(* Logix 5000 project; controller NXFE2_EDS_AOI_sample_RSLogix_V31 vendor 1 type 14 code 92 rev 31.11; software revision 31.00; part 2 of 4 *)

ADD_ON_INSTRUCTION AMCI_NXFE2_Home_CW   (* revision 1.0, vendor AMCI, ExecuteEnableInFalse *)
VAR_INPUT
   Axis_Status_Bits : INT; {required}
   Programmed_Speed : DINT; {required}
   Acceleration : INT; {required}
   Deceleration : INT; {required}
END_VAR
VAR_IN_OUT
   NXFE2_output_data : _000A:NXFE2_0986AEB4:O:0; {required}
END_VAR
VAR_OUTPUT
   EN : BOOL; {access Read Only, visible}
   ER : BOOL; {access Read Only, visible}
END_VAR
VAR
   command_data_block : INT[10];
        [1]   // Command Bits LSW
        [3]   // Lower Target Position
        [5]   // Lower Programmed Speed
        [0]   // Command Bits MSW
        [2]   // Upper Target Position
        [4]   // Upper Programmed Speed
END_VAR

ROUTINE EnableInFalse   (* ladder *)
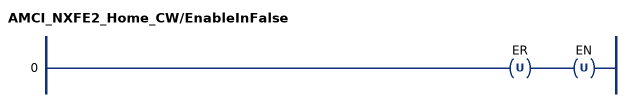
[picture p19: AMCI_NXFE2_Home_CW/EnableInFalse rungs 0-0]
   0: OTU(ER)OTU(EN);
END_ROUTINE

ROUTINE Logic   (* ladder *)
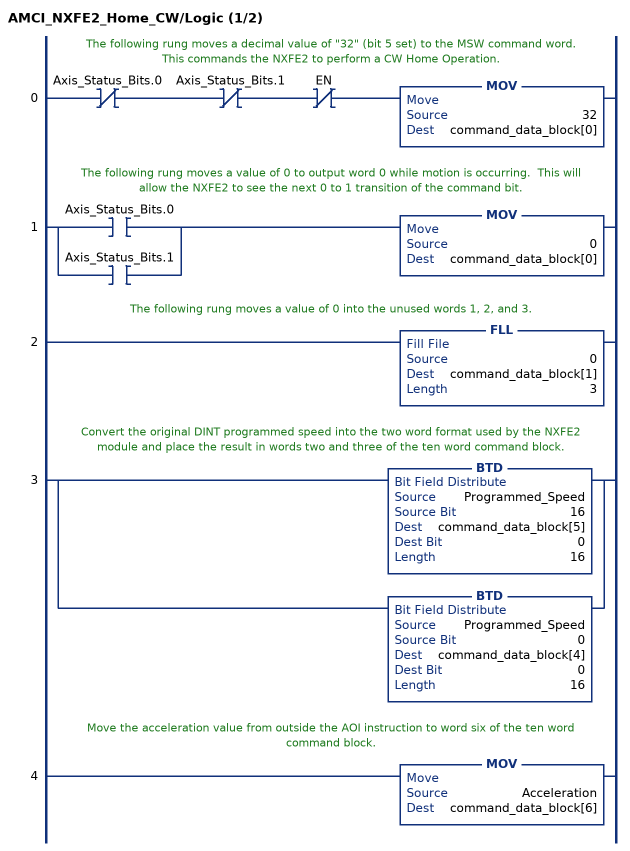
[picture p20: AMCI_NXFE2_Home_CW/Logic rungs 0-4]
   // The following rung moves a decimal value of "32" (bit 5 set) to the MSW command word.  This commands the NXFE2 to perform a CW Home Operation.
   0: XIO(Axis_Status_Bits.0)XIO(Axis_Status_Bits.1)XIO(EN)MOV(32,command_data_block[0]);
   // The following rung moves a value of 0 to output word 0 while motion is occurring.  This will allow the NXFE2 to see the next 0 to 1 transition of the command bit.
   1: [XIC(Axis_Status_Bits.0) ,XIC(Axis_Status_Bits.1) ]MOV(0,command_data_block[0]);
   // The following rung moves a value of 0 into the unused words 1, 2, and 3.
   2: FLL(0,command_data_block[1],3);
   // Convert the original DINT programmed speed into the two word format used by the NXFE2 module and place the result in words two and three of the ten word command block.
   3: [BTD(Programmed_Speed,16,command_data_block[5],0,16) ,BTD(Programmed_Speed,0,command_data_block[4],0,16) ];
   // Move the acceleration value from outside the AOI instruction to word six of the ten word command block.
   4: MOV(Acceleration,command_data_block[6]);
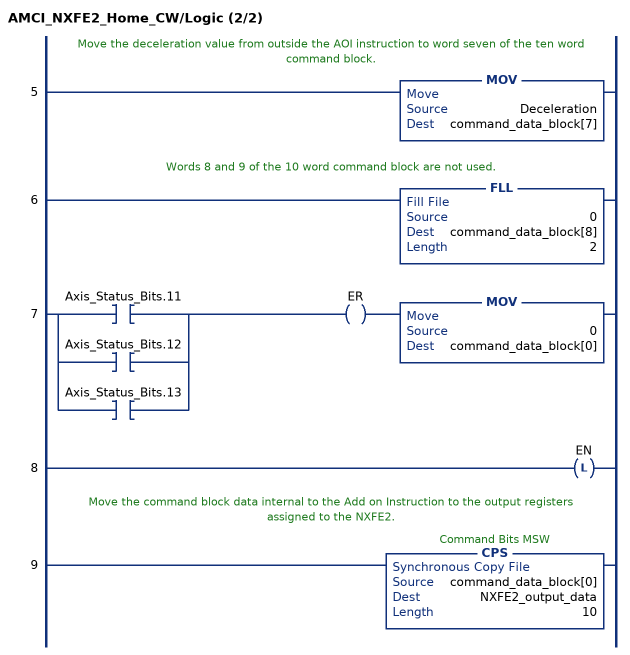
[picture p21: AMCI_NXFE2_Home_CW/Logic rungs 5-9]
   // Move the deceleration value from outside the AOI instruction to word seven of the ten word command block.
   5: MOV(Deceleration,command_data_block[7]);
   // Words 8 and 9 of the 10 word command block are not used.
   6: FLL(0,command_data_block[8],2);
   7: [XIC(Axis_Status_Bits.11) ,XIC(Axis_Status_Bits.12) ,XIC(Axis_Status_Bits.13) ]OTE(ER)MOV(0,command_data_block[0]);
   8: OTL(EN);
   // Move the command block data internal to the Add on Instruction to the output registers assigned to the NXFE2.
   9: CPS(command_data_block[0],NXFE2_output_data,10);
END_ROUTINE
END_ADD_ON_INSTRUCTION

ADD_ON_INSTRUCTION AMCI_NXFE2_Immediate_Stop   (* revision 1.1, vendor AMCI *)
// Revision note:
// Version 1.1 added the slot_axis number and the input parameters can now be tags or discrete values.
VAR_IN_OUT
   NXFE2_output_data : _000A:NXFE2_0986AEB4:O:0; {required}
END_VAR
VAR
   command_data_block : INT[10];
        [1]   // Command Bits LSW
        [3]   // Lower Target Position
        [5]   // Lower Programmed Speed
        [0]   // Command Bits MSW
        [2]   // Upper Target Position
        [4]   // Upper Programmed Speed
END_VAR

ROUTINE Logic   (* ladder *)
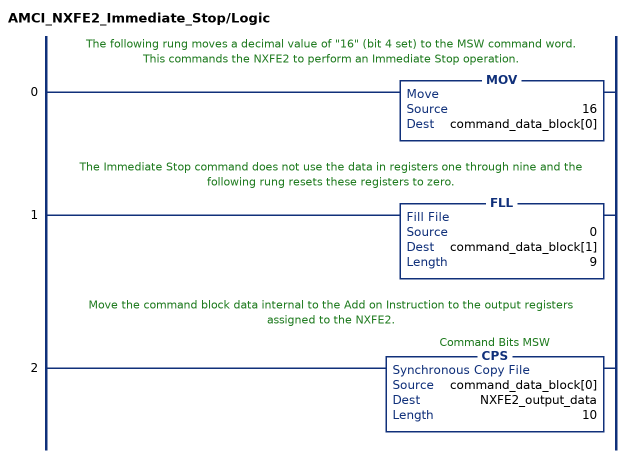
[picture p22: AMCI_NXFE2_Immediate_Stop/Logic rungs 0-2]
   // The following rung moves a decimal value of "16" (bit 4 set) to the MSW command word.  This commands the NXFE2 to perform an Immediate Stop operation.
   0: MOV(16,command_data_block[0]);
   // The Immediate Stop command does not use the data in registers one through nine and the following rung resets these registers to zero.
   1: FLL(0,command_data_block[1],9);
   // Move the command block data internal to the Add on Instruction to the output registers assigned to the NXFE2.
   2: CPS(command_data_block[0],NXFE2_output_data,10);
END_ROUTINE
END_ADD_ON_INSTRUCTION

ADD_ON_INSTRUCTION AMCI_NXFE2_Jog_CCW   (* revision 1.0, vendor AMCI, ExecuteEnableInFalse *)
VAR_INPUT
   Axis_Status_Bits : DINT; {required}
        .1   // Set when moving CCW
   _0_normal_1_S_curve_acceleration : BOOL;
   _0_Triangular_1_Trapezoidal_S_Curve : BOOL;
   Programmed_Speed : DINT; {required}
   Acceleration : INT; {required}
   Deceleration : INT; {required}
END_VAR
VAR_IN_OUT
   NXFE2_output_data : _000A:NXFE2_0986AEB4:O:0; {required}
END_VAR
VAR_OUTPUT
   EN : BOOL; {access Read Only, visible}
   Jog_CCW_Occurring : BOOL; {access Read Only, visible}
   ER : BOOL; {access Read Only, visible}
END_VAR
VAR
   command_data_block : INT[10];
        [1]   // Command Bits LSW
        [3]   // Lower Target Position
        [5]   // Lower Programmed Speed
        [0]   // Command Bits MSW
        [4]   // Upper Programmed Speed
END_VAR

ROUTINE EnableInFalse   (* ladder *)
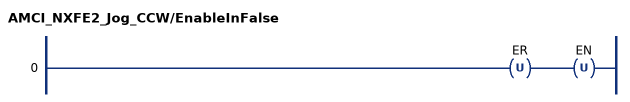
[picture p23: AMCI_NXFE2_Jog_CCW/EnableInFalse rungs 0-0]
   0: OTU(ER)OTU(EN);
END_ROUTINE

ROUTINE Logic   (* ladder *)
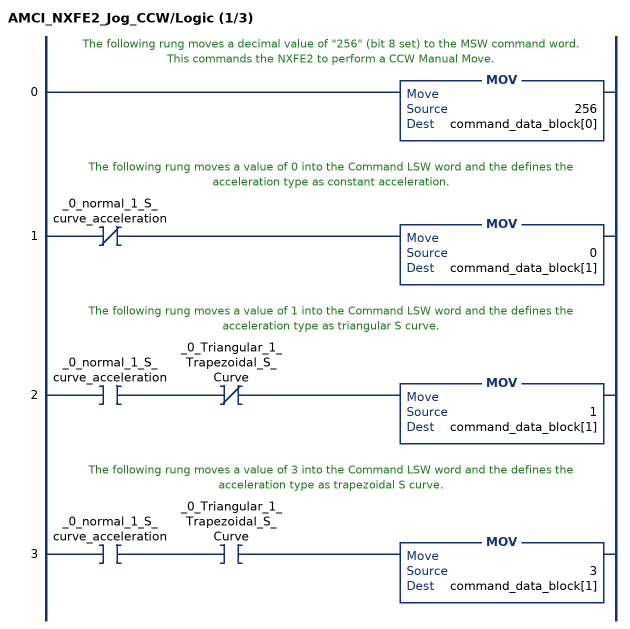
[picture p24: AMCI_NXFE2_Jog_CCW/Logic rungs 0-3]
   // The following rung moves a decimal value of "256" (bit 8 set) to the MSW command word.  This commands the NXFE2 to perform a CCW Manual Move.
   0: MOV(256,command_data_block[0]);
   // The following rung moves a value of 0 into the Command LSW word and the defines the acceleration type as constant acceleration.
   1: XIO(_0_normal_1_S_curve_acceleration)MOV(0,command_data_block[1]);
   // The following rung moves a value of 1 into the Command LSW word and the defines the acceleration type as triangular S curve.
   2: XIC(_0_normal_1_S_curve_acceleration)XIO(_0_Triangular_1_Trapezoidal_S_Curve)MOV(1,command_data_block[1]);
   // The following rung moves a value of 3 into the Command LSW word and the defines the acceleration type as trapezoidal S curve.
   3: XIC(_0_normal_1_S_curve_acceleration)XIC(_0_Triangular_1_Trapezoidal_S_Curve)MOV(3,command_data_block[1]);
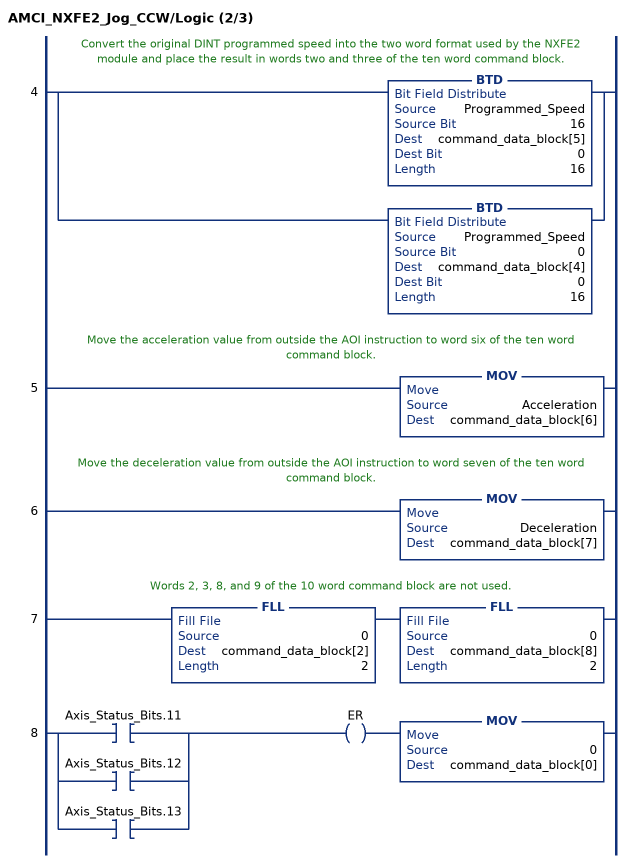
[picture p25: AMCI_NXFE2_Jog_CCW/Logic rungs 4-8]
   // Convert the original DINT programmed speed into the two word format used by the NXFE2 module and place the result in words two and three of the ten word command block.
   4: [BTD(Programmed_Speed,16,command_data_block[5],0,16) ,BTD(Programmed_Speed,0,command_data_block[4],0,16) ];
   // Move the acceleration value from outside the AOI instruction to word six of the ten word command block.
   5: MOV(Acceleration,command_data_block[6]);
   // Move the deceleration value from outside the AOI instruction to word seven of the ten word command block.
   6: MOV(Deceleration,command_data_block[7]);
   // Words 2, 3, 8, and 9 of the 10 word command block are not used.
   7: FLL(0,command_data_block[2],2)FLL(0,command_data_block[8],2);
   8: [XIC(Axis_Status_Bits.11) ,XIC(Axis_Status_Bits.12) ,XIC(Axis_Status_Bits.13) ]OTE(ER)MOV(0,command_data_block[0]);
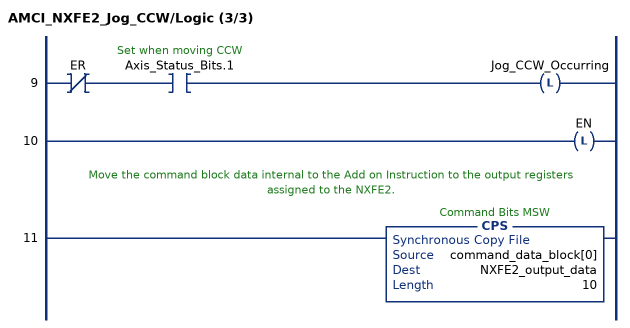
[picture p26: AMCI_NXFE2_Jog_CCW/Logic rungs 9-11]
   9: XIO(ER)XIC(Axis_Status_Bits.1)OTL(Jog_CCW_Occurring);
   10: OTL(EN);
   // Move the command block data internal to the Add on Instruction to the output registers assigned to the NXFE2.
   11: CPS(command_data_block[0],NXFE2_output_data,10);
END_ROUTINE
END_ADD_ON_INSTRUCTION

ADD_ON_INSTRUCTION AMCI_NXFE2_Jog_CW   (* revision 1.0, vendor AMCI, ExecuteEnableInFalse *)
VAR_INPUT
   Axis_Status_Bits : INT; {required}
   _0_normal_1_S_Curve_Acceleration : BOOL;
   _0_Triangular_1_Trapezoidal_S_Curve : BOOL;
   Programmed_Speed : DINT; {required}
   Acceleration : INT; {required}
   Deceleration : INT; {required}
END_VAR
VAR_IN_OUT
   NXFE2_output_data : _000A:NXFE2_0986AEB4:O:0; {required}
END_VAR
VAR_OUTPUT
   EN : BOOL; {access Read Only, visible}
   Jog_CW_Occurring : BOOL; {access Read Only, visible}
   ER : BOOL; {access Read Only, visible}
END_VAR
VAR
   command_data_block : INT[10];
        [1]   // Command Bits LSW
        [3]   // Lower Target Position
        [5]   // Lower Programmed Speed
        [0]   // Command Bits MSW
        [4]   // Upper Programmed Speed
END_VAR

ROUTINE EnableInFalse   (* ladder *)
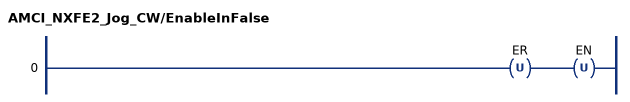
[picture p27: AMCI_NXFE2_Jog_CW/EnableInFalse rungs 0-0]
   0: OTU(ER)OTU(EN);
END_ROUTINE

ROUTINE Logic   (* ladder *)
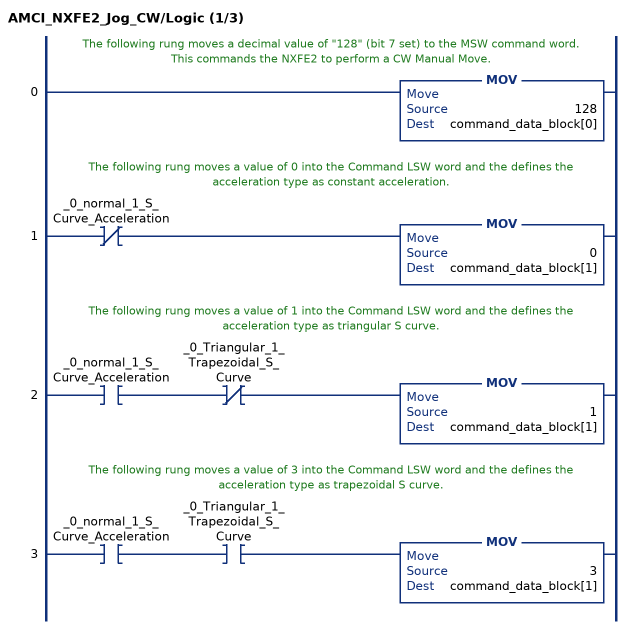
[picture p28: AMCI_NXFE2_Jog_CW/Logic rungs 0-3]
   // The following rung moves a decimal value of "128" (bit 7 set) to the MSW command word.  This commands the NXFE2 to perform a CW Manual Move.
   0: MOV(128,command_data_block[0]);
   // The following rung moves a value of 0 into the Command LSW word and the defines the acceleration type as constant acceleration.
   1: XIO(_0_normal_1_S_Curve_Acceleration)MOV(0,command_data_block[1]);
   // The following rung moves a value of 1 into the Command LSW word and the defines the acceleration type as triangular S curve.
   2: XIC(_0_normal_1_S_Curve_Acceleration)XIO(_0_Triangular_1_Trapezoidal_S_Curve)MOV(1,command_data_block[1]);
   // The following rung moves a value of 3 into the Command LSW word and the defines the acceleration type as trapezoidal S curve.
   3: XIC(_0_normal_1_S_Curve_Acceleration)XIC(_0_Triangular_1_Trapezoidal_S_Curve)MOV(3,command_data_block[1]);
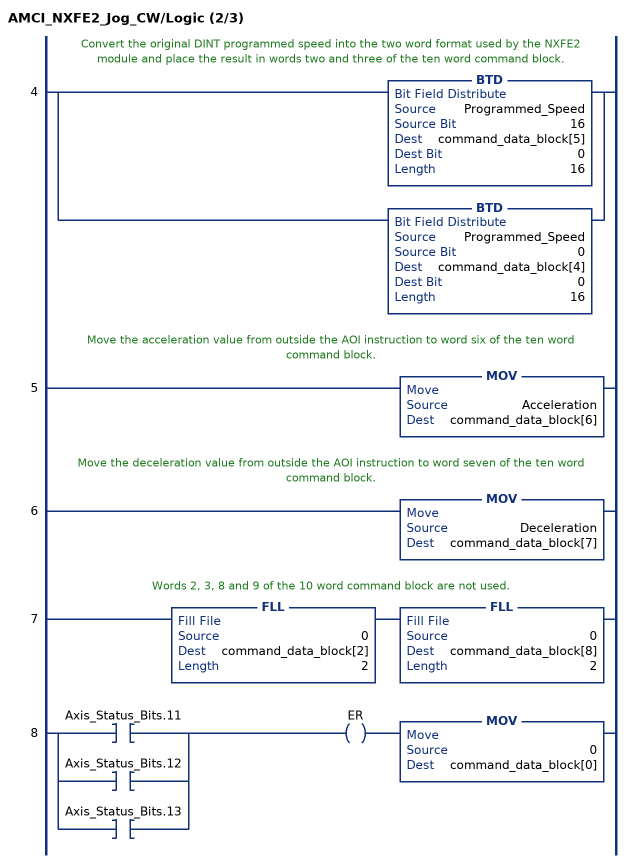
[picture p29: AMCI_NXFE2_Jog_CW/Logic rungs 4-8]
   // Convert the original DINT programmed speed into the two word format used by the NXFE2 module and place the result in words two and three of the ten word command block.
   4: [BTD(Programmed_Speed,16,command_data_block[5],0,16) ,BTD(Programmed_Speed,0,command_data_block[4],0,16) ];
   // Move the acceleration value from outside the AOI instruction to word six of the ten word command block.
   5: MOV(Acceleration,command_data_block[6]);
   // Move the deceleration value from outside the AOI instruction to word seven of the ten word command block.
   6: MOV(Deceleration,command_data_block[7]);
   // Words 2, 3, 8 and 9 of the 10 word command block are not used.
   7: FLL(0,command_data_block[2],2)FLL(0,command_data_block[8],2);
   8: [XIC(Axis_Status_Bits.11) ,XIC(Axis_Status_Bits.12) ,XIC(Axis_Status_Bits.13) ]OTE(ER)MOV(0,command_data_block[0]);
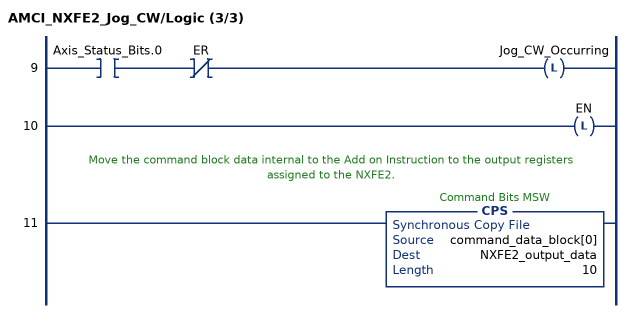
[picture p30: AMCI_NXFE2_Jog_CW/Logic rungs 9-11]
   9: XIC(Axis_Status_Bits.0)XIO(ER)OTL(Jog_CW_Occurring);
   10: OTL(EN);
   // Move the command block data internal to the Add on Instruction to the output registers assigned to the NXFE2.
   11: CPS(command_data_block[0],NXFE2_output_data,10);
END_ROUTINE
END_ADD_ON_INSTRUCTION

ADD_ON_INSTRUCTION AMCI_NXFE2_Minimum_Registration_Distance   (* revision 1.0, vendor AMCI *)
VAR_INPUT
   Minimum_Registration_Distance : DINT; {required}
END_VAR
VAR_IN_OUT
   NXFE2_output_data : _000A:NXFE2_0986AEB4:O:0; {required}
END_VAR
VAR
   command_data_block : INT[10];
        [1]   // Command Bits LSW
        [3]   // Lower Target Position
        [5]   // Lower Programmed Speed
        [0]   // Command Bits MSW
        [2]   // Upper Target Position
        [4]   // Upper Programmed Speed
END_VAR

ROUTINE Logic   (* ladder *)
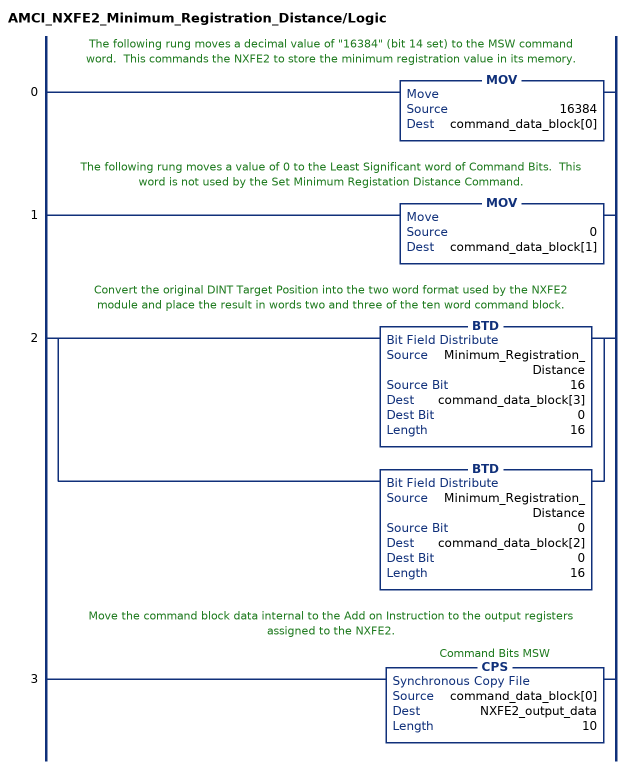
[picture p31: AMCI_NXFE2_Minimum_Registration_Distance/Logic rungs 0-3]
   // The following rung moves a decimal value of "16384" (bit 14 set) to the MSW command word.  This commands the NXFE2 to store the minimum registration value in its memory.
   0: MOV(16384,command_data_block[0]);
   // The following rung moves a value of 0 to the Least Significant word of Command Bits.  This word is not used by the Set Minimum Registation Distance Command.
   1: MOV(0,command_data_block[1]);
   // Convert the original DINT Target Position into the two word format used by the NXFE2 module and place the result in words two and three of the ten word command block.
   2: [BTD(Minimum_Registration_Distance,16,command_data_block[3],0,16) ,BTD(Minimum_Registration_Distance,0,command_data_block[2],0,16) ];
   // Move the command block data internal to the Add on Instruction to the output registers assigned to the NXFE2.
   3: CPS(command_data_block[0],NXFE2_output_data,10);
END_ROUTINE
END_ADD_ON_INSTRUCTION

ADD_ON_INSTRUCTION AMCI_NXFE2_Preset_Encoder_Position   (* revision 1.0, vendor AMCI *)
VAR_INPUT
   Target_Position : DINT; {required}
END_VAR
VAR_IN_OUT
   NXFE2_output_data : _000A:NXFE2_0986AEB4:O:0; {required}
END_VAR
VAR
   command_data_block : INT[10];
        [5]   // Lower Programmed Speed
        [0]   // Command Bits MSW
        [1]   // Command Bits LSW
        [3]   // Lower Target Position
        [2]   // Upper Target Position
        [4]   // Upper Programmed Speed
END_VAR

ROUTINE Logic   (* ladder *)
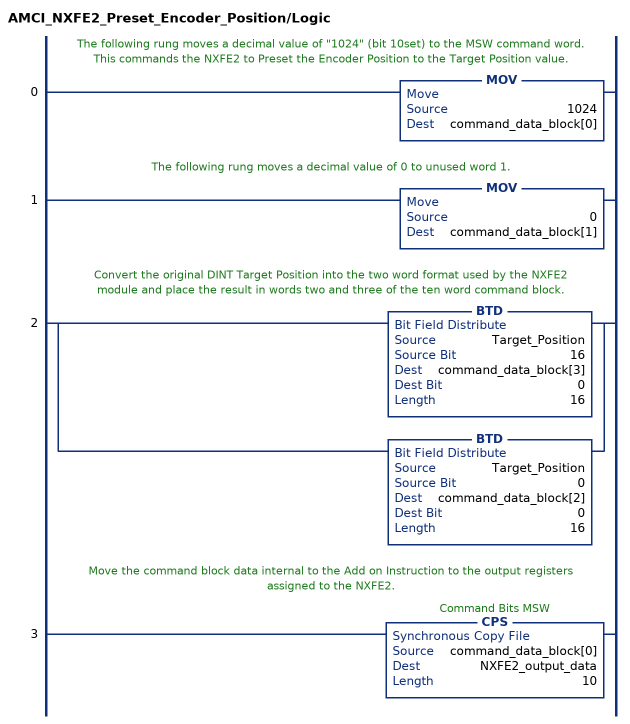
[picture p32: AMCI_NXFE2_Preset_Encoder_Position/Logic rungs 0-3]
   // The following rung moves a decimal value of "1024" (bit 10set) to the MSW command word.  This commands the NXFE2 to Preset the Encoder Position to the Target Position value.
   0: MOV(1024,command_data_block[0]);
   // The following rung moves a decimal value of 0 to unused word 1.
   1: MOV(0,command_data_block[1]);
   // Convert the original DINT Target Position into the two word format used by the NXFE2 module and place the result in words two and three of the ten word command block.
   2: [BTD(Target_Position,16,command_data_block[3],0,16) ,BTD(Target_Position,0,command_data_block[2],0,16) ];
   // Move the command block data internal to the Add on Instruction to the output registers assigned to the NXFE2.
   3: CPS(command_data_block[0],NXFE2_output_data,10);
END_ROUTINE
END_ADD_ON_INSTRUCTION

ADD_ON_INSTRUCTION AMCI_NXFE2_Preset_Position   (* revision 1.0, vendor AMCI *)
VAR_INPUT
   Target_Position : DINT; {required}
END_VAR
VAR_IN_OUT
   NXFE2_output_data : _000A:NXFE2_0986AEB4:O:0; {required}
END_VAR
VAR
   command_data_block : INT[10];
        [1]   // Command Bits LSW
        [3]   // Lower Target Position
        [5]   // Lower Programmed Speed
        [2]   // Upper Target Position
        [4]   // Upper Programmed Speed
        [0]   // Command Bits MSW
END_VAR

ROUTINE Logic   (* ladder *)
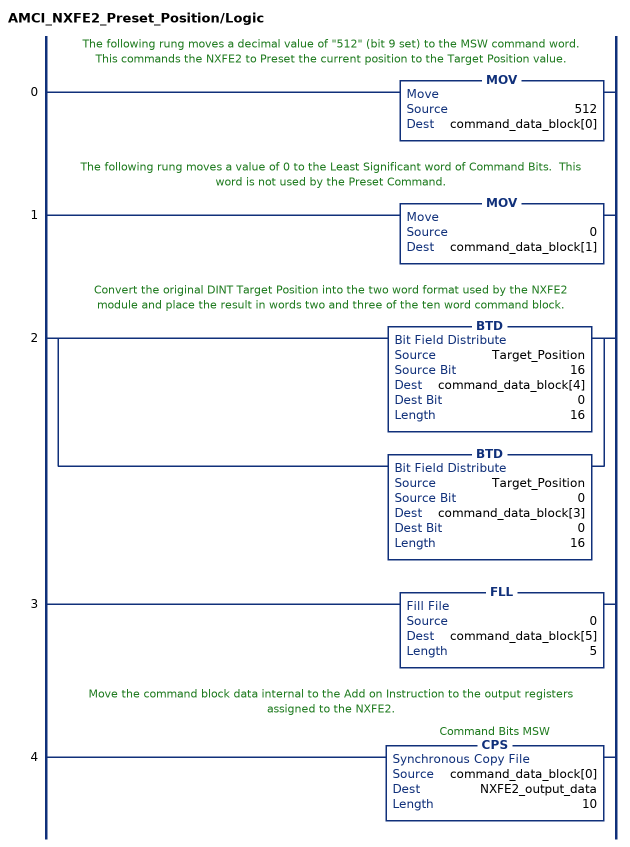
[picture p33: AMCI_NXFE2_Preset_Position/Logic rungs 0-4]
   // The following rung moves a decimal value of "512" (bit 9 set) to the MSW command word.  This commands the NXFE2 to Preset the current position to the Target Position value.
   0: MOV(512,command_data_block[0]);
   // The following rung moves a value of 0 to the Least Significant word of Command Bits.  This word is not used by the Preset Command.
   1: MOV(0,command_data_block[1]);
   // Convert the original DINT Target Position into the two word format used by the NXFE2 module and place the result in words two and three of the ten word command block.
   2: [BTD(Target_Position,16,command_data_block[4],0,16) ,BTD(Target_Position,0,command_data_block[3],0,16) ];
   3: FLL(0,command_data_block[5],5);
   // Move the command block data internal to the Add on Instruction to the output registers assigned to the NXFE2.
   4: CPS(command_data_block[0],NXFE2_output_data,10);
END_ROUTINE
END_ADD_ON_INSTRUCTION

ADD_ON_INSTRUCTION AMCI_NXFE2_Program_Blend_Move   (* revision 1.0, ExecuteEnableInFalse *)
VAR_INPUT
   Status_Bits_MSW : INT; {required}
        .9   // Set when invalid profile error
   Status_Bits_LSW : INT; {required}
        .9   // The NXFE2 module sets this bit to Acknowledge the receipt of a blend move programming block
   Number_of_Segments : INT; {required}
   Final_Move_Deceleration : INT; {required}
   Acceleration_Type_segments_9_to_16 : INT;
   Acceleration_Type_segments_1_to_8 : INT;
   Segment_1_Distance : DINT; {required}
   Segment_1_Programmed_Speed : DINT; {required}
   Segment_1_Acceleration_Deceleration : INT; {required}
   Segment_2_Distance : DINT; {required}
   Segment_2_Programmed_Speed : DINT; {required}
   Segment_2_Acceleration_Deceleration : INT; {required}
   Segment_3_Distance : DINT; {required}
   Segment_3_Programmed_Speed : DINT; {required}
   Segment_3_Acceleration_Deceleration : INT; {required}
   Segment_4_Distance : DINT; {required}
   Segment_4_Programmed_Speed : DINT; {required}
   Segment_4_Acceleration_Deceleration : INT; {required}
   Segment_5_Distance : DINT; {required}
   Segment_5_Programmed_Speed : DINT; {required}
   Segment_5_Acceleration_Deceleration : INT; {required}
   Segment_6_Distance : DINT; {required}
   Segment_6_Programmed_Speed : DINT; {required}
   Segment_6_Acceleration_Deceleration : INT; {required}
   Segment_7_Distance : DINT; {required}
   Segment_7_Programmed_Speed : DINT; {required}
   Segment_7_Acceleration_Deceleration : INT; {required}
   Segment_8_Distance : DINT; {required}
   Segment_8_Programmed_Speed : DINT; {required}
   Segment_8_Acceleration_Deceleration : INT; {required}
   Segment_9_Distance : DINT; {required}
   Segment_9_Programmed_Speed : DINT; {required}
   Segment_9_Acceleration_Deceleration : INT; {required}
   Segment_10_Distance : DINT; {required}
   Segment_10_Programmed_Speed : DINT; {required}
   Segment_10_Acceleration_Deceleration : INT; {required}
   Segment_11_Distance : DINT; {required}
   Segment_11_Programmed_Speed : DINT; {required}
   Segment_11_Acceleration_Deceleration : INT; {required}
   Segment_12_Distance : DINT; {required}
   Segment_12_Programmed_Speed : DINT; {required}
   Segment_12_Acceleration_Deceleration : INT; {required}
   Segment_13_Distance : DINT; {required}
   Segment_13_Programmed_Speed : DINT; {required}
   Segment_13_Acceleration_Deceleration : INT; {required}
   Segment_14_Distance : DINT; {required}
   Segment_14_Programmed_Speed : DINT; {required}
   Segment_14_Acceleration_Deceleration : INT; {required}
   Segment_15_Distance : DINT; {required}
   Segment_15_Programmed_Speed : DINT; {required}
   Segment_15_Acceleration_Deceleration : INT; {required}
   Segment_16_Distance : DINT; {required}
   Segment_16_Programmed_Speed : DINT; {required}
   Segment_16_Acceleration_Deceleration : INT; {required}
END_VAR
VAR_IN_OUT
   NXFE2_output_data : _000A:NXFE2_0986AEB4:O:0; {required}
END_VAR
VAR_OUTPUT
   Blend_Move_Programmed : BOOL; {access Read Only, visible}
END_VAR
VAR
   command_data_block : INT[10];
   Blend_Move_setup : INT[10] := ([1] := -32640);
   Blend_Move_counter : COUNTER;
   Programmed_Speed : DINT;
   Distance : DINT;
END_VAR

ROUTINE EnableInFalse   (* ladder *)
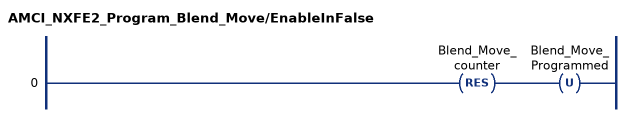
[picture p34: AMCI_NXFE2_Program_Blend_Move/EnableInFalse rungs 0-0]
   0: RES(Blend_Move_counter)OTU(Blend_Move_Programmed);
END_ROUTINE

ROUTINE Logic   (* ladder *)
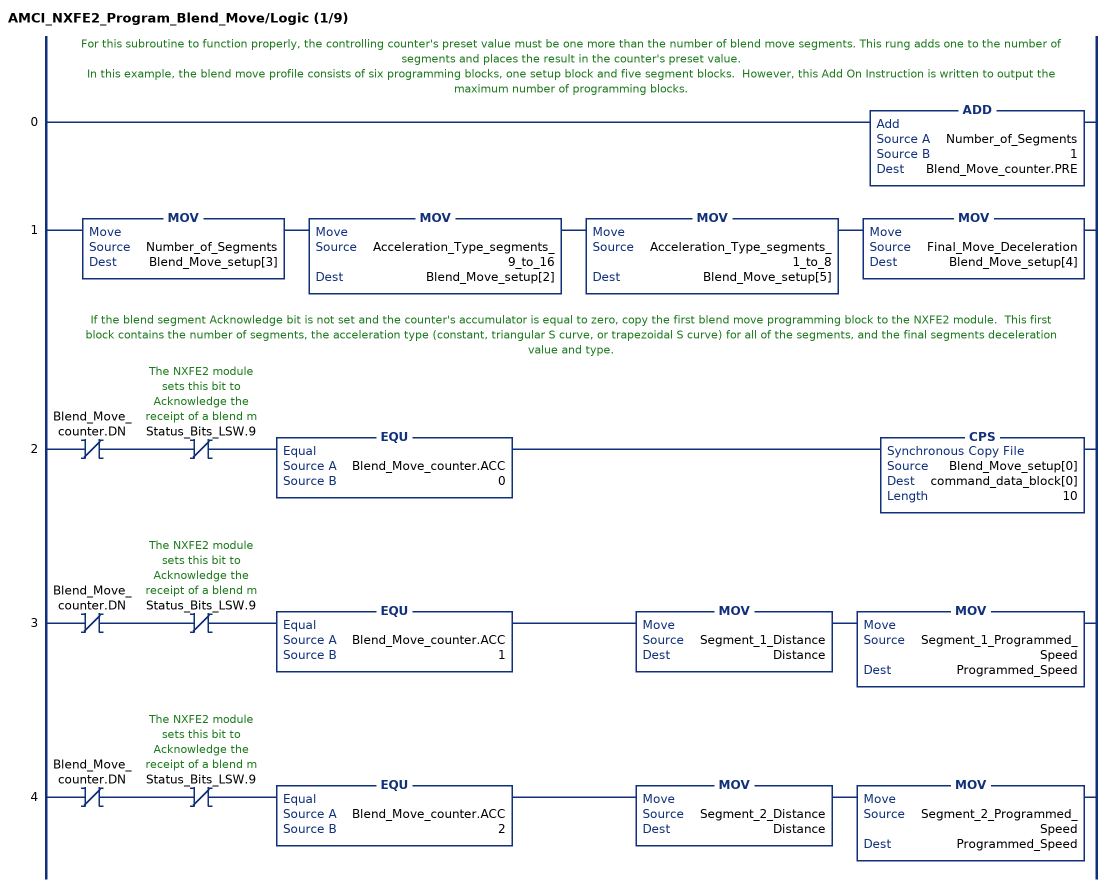
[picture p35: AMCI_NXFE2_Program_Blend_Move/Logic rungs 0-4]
   // For this subroutine to function properly, the controlling counter's preset value must be one more than the number of blend move segments. This rung adds one to the number of segments and places the result in the counter's preset value.
   // In this example, the blend move profile consists of six programming blocks, one setup block and five segment blocks.  However, this Add On Instruction is written to output the maximum number of programming blocks.
   0: ADD(Number_of_Segments,1,Blend_Move_counter.PRE);
   1: MOV(Number_of_Segments,Blend_Move_setup[3])MOV(Acceleration_Type_segments_9_to_16,Blend_Move_setup[2])MOV(Acceleration_Type_segments_1_to_8,Blend_Move_setup[5])MOV(Final_Move_Deceleration,Blend_Move_setup[4]);
   // If the blend segment Acknowledge bit is not set and the counter's accumulator is equal to zero, copy the first blend move programming block to the NXFE2 module.  This first block contains the number of segments, the acceleration type (constant, triangular S curve, or trapezoidal S curve) for all of the segments, and the final segments deceleration value and type.
   2: XIO(Blend_Move_counter.DN)XIO(Status_Bits_LSW.9)EQU(Blend_Move_counter.ACC,0)CPS(Blend_Move_setup[0],command_data_block[0],10);
   3: XIO(Blend_Move_counter.DN)XIO(Status_Bits_LSW.9)EQU(Blend_Move_counter.ACC,1)MOV(Segment_1_Distance,Distance)MOV(Segment_1_Programmed_Speed,Programmed_Speed);
   4: XIO(Blend_Move_counter.DN)XIO(Status_Bits_LSW.9)EQU(Blend_Move_counter.ACC,2)MOV(Segment_2_Distance,Distance)MOV(Segment_2_Programmed_Speed,Programmed_Speed);
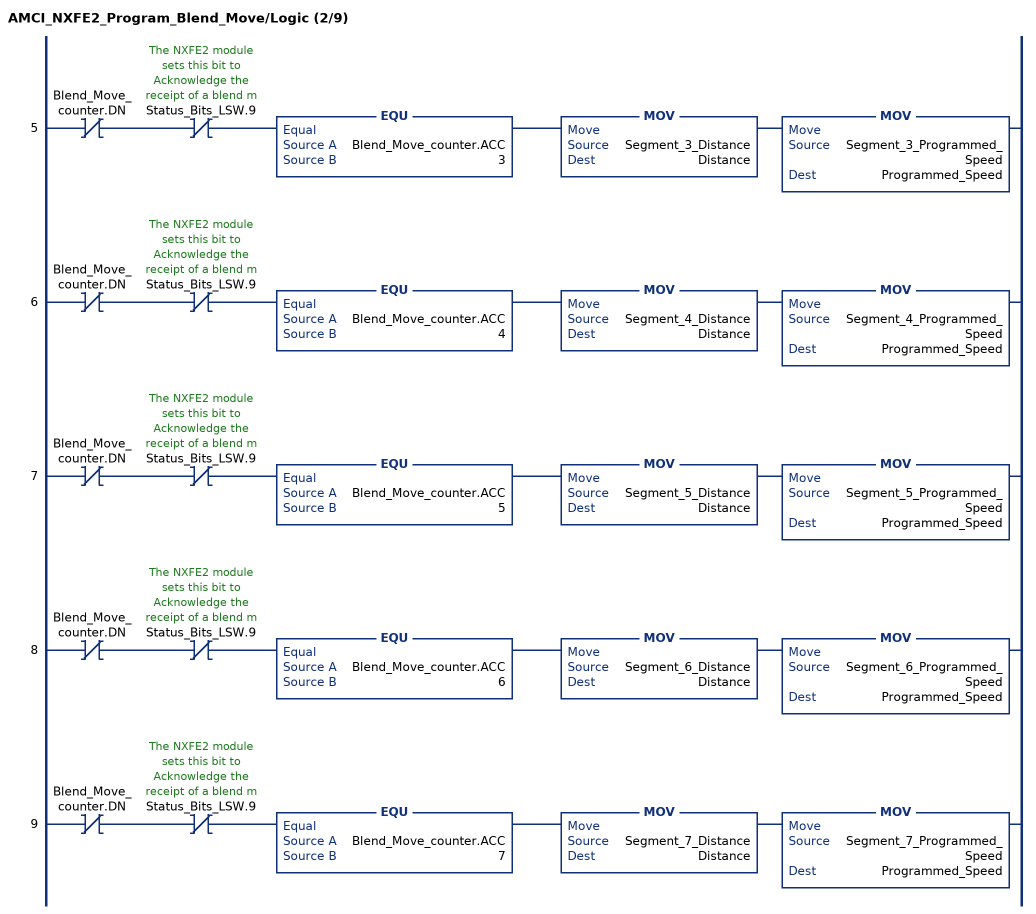
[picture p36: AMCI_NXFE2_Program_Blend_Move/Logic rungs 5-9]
   5: XIO(Blend_Move_counter.DN)XIO(Status_Bits_LSW.9)EQU(Blend_Move_counter.ACC,3)MOV(Segment_3_Distance,Distance)MOV(Segment_3_Programmed_Speed,Programmed_Speed);
   6: XIO(Blend_Move_counter.DN)XIO(Status_Bits_LSW.9)EQU(Blend_Move_counter.ACC,4)MOV(Segment_4_Distance,Distance)MOV(Segment_4_Programmed_Speed,Programmed_Speed);
   7: XIO(Blend_Move_counter.DN)XIO(Status_Bits_LSW.9)EQU(Blend_Move_counter.ACC,5)MOV(Segment_5_Distance,Distance)MOV(Segment_5_Programmed_Speed,Programmed_Speed);
   8: XIO(Blend_Move_counter.DN)XIO(Status_Bits_LSW.9)EQU(Blend_Move_counter.ACC,6)MOV(Segment_6_Distance,Distance)MOV(Segment_6_Programmed_Speed,Programmed_Speed);
   9: XIO(Blend_Move_counter.DN)XIO(Status_Bits_LSW.9)EQU(Blend_Move_counter.ACC,7)MOV(Segment_7_Distance,Distance)MOV(Segment_7_Programmed_Speed,Programmed_Speed);
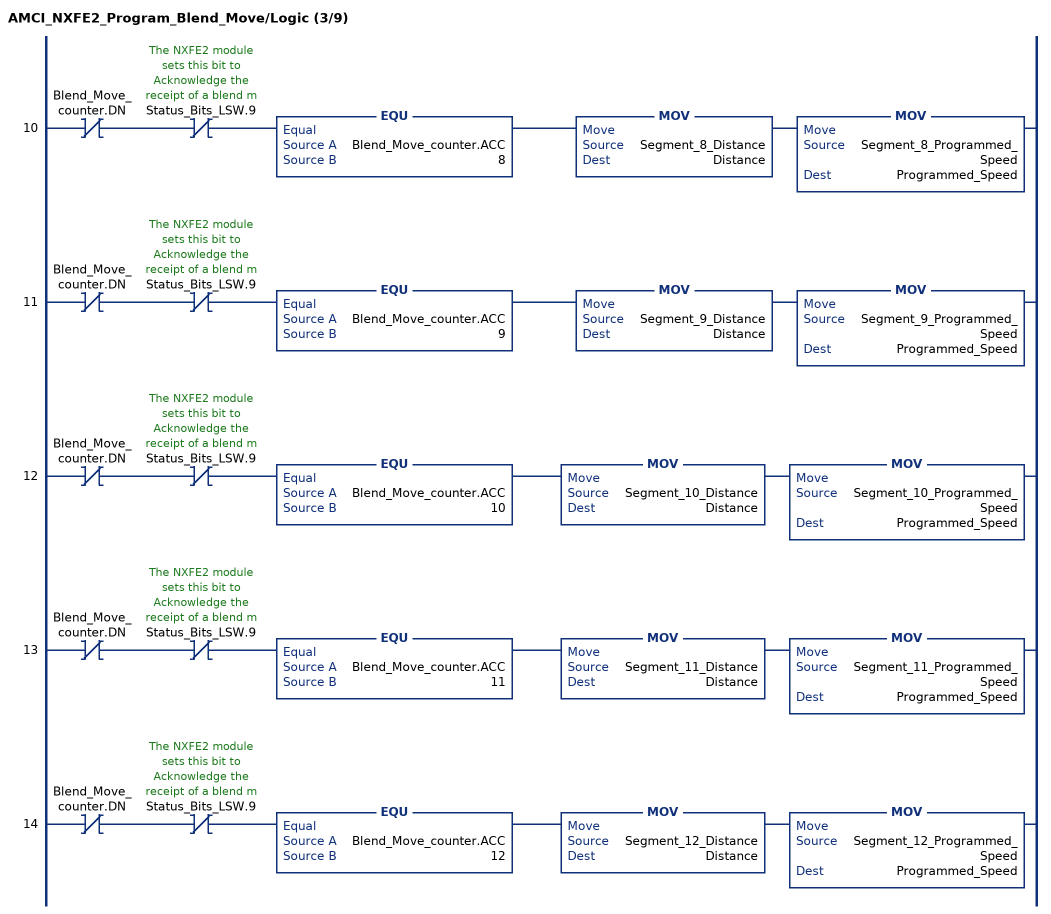
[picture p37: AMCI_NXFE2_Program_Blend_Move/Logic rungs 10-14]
   10: XIO(Blend_Move_counter.DN)XIO(Status_Bits_LSW.9)EQU(Blend_Move_counter.ACC,8)MOV(Segment_8_Distance,Distance)MOV(Segment_8_Programmed_Speed,Programmed_Speed);
   11: XIO(Blend_Move_counter.DN)XIO(Status_Bits_LSW.9)EQU(Blend_Move_counter.ACC,9)MOV(Segment_9_Distance,Distance)MOV(Segment_9_Programmed_Speed,Programmed_Speed);
   12: XIO(Blend_Move_counter.DN)XIO(Status_Bits_LSW.9)EQU(Blend_Move_counter.ACC,10)MOV(Segment_10_Distance,Distance)MOV(Segment_10_Programmed_Speed,Programmed_Speed);
   13: XIO(Blend_Move_counter.DN)XIO(Status_Bits_LSW.9)EQU(Blend_Move_counter.ACC,11)MOV(Segment_11_Distance,Distance)MOV(Segment_11_Programmed_Speed,Programmed_Speed);
   14: XIO(Blend_Move_counter.DN)XIO(Status_Bits_LSW.9)EQU(Blend_Move_counter.ACC,12)MOV(Segment_12_Distance,Distance)MOV(Segment_12_Programmed_Speed,Programmed_Speed);
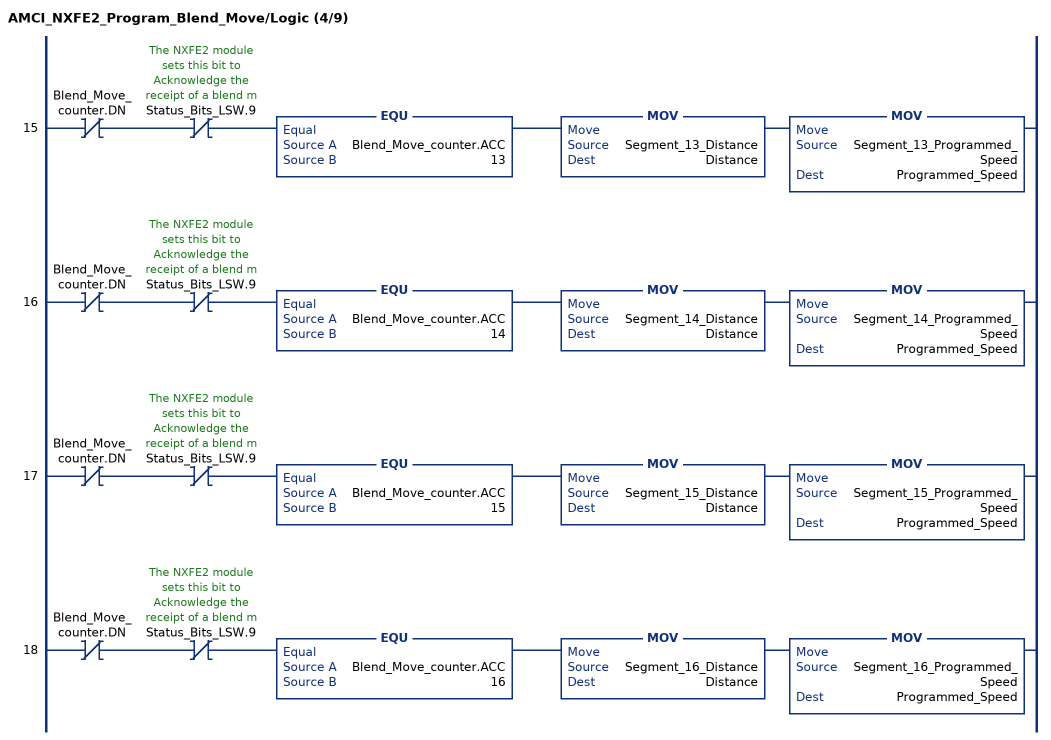
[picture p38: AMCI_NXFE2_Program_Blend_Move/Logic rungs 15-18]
   15: XIO(Blend_Move_counter.DN)XIO(Status_Bits_LSW.9)EQU(Blend_Move_counter.ACC,13)MOV(Segment_13_Distance,Distance)MOV(Segment_13_Programmed_Speed,Programmed_Speed);
   16: XIO(Blend_Move_counter.DN)XIO(Status_Bits_LSW.9)EQU(Blend_Move_counter.ACC,14)MOV(Segment_14_Distance,Distance)MOV(Segment_14_Programmed_Speed,Programmed_Speed);
   17: XIO(Blend_Move_counter.DN)XIO(Status_Bits_LSW.9)EQU(Blend_Move_counter.ACC,15)MOV(Segment_15_Distance,Distance)MOV(Segment_15_Programmed_Speed,Programmed_Speed);
   18: XIO(Blend_Move_counter.DN)XIO(Status_Bits_LSW.9)EQU(Blend_Move_counter.ACC,16)MOV(Segment_16_Distance,Distance)MOV(Segment_16_Programmed_Speed,Programmed_Speed);
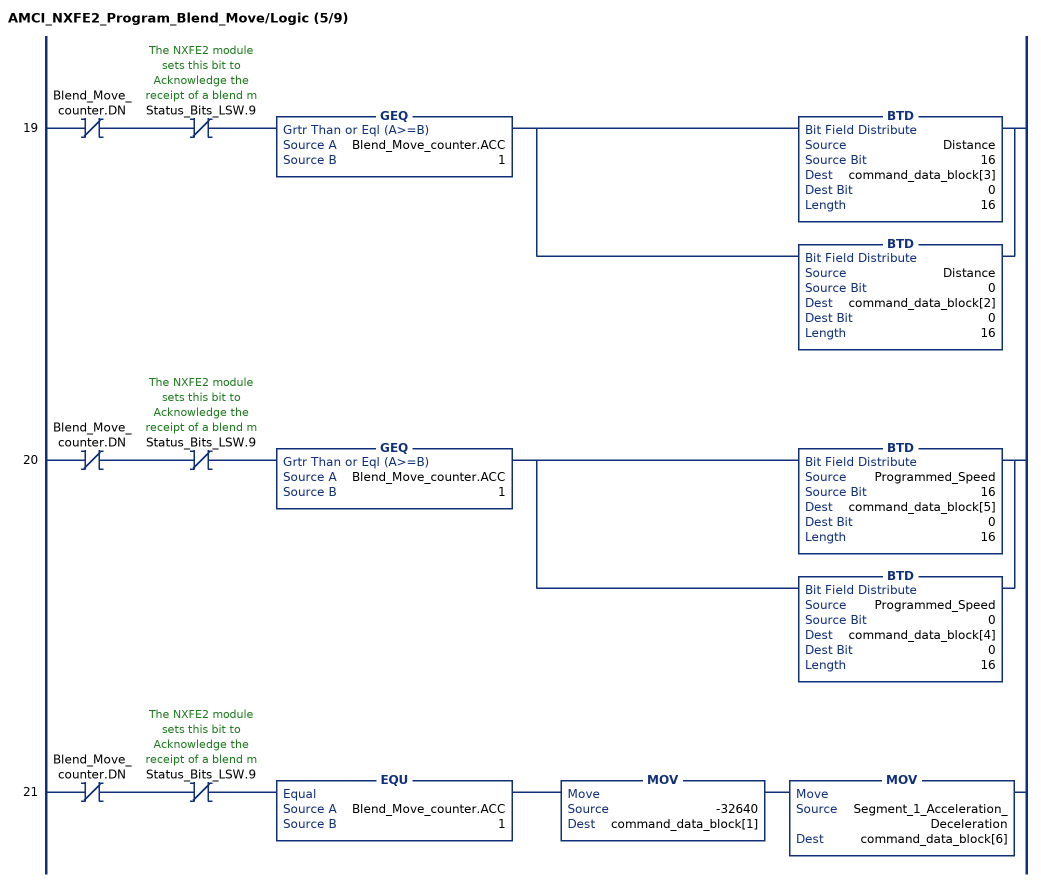
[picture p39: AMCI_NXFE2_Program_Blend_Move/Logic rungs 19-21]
   19: XIO(Blend_Move_counter.DN)XIO(Status_Bits_LSW.9)GEQ(Blend_Move_counter.ACC,1)[BTD(Distance,16,command_data_block[3],0,16) ,BTD(Distance,0,command_data_block[2],0,16) ];
   20: XIO(Blend_Move_counter.DN)XIO(Status_Bits_LSW.9)GEQ(Blend_Move_counter.ACC,1)[BTD(Programmed_Speed,16,command_data_block[5],0,16) ,BTD(Programmed_Speed,0,command_data_block[4],0,16) ];
   21: XIO(Blend_Move_counter.DN)XIO(Status_Bits_LSW.9)EQU(Blend_Move_counter.ACC,1)MOV(-32640,command_data_block[1])MOV(Segment_1_Acceleration_Deceleration,command_data_block[6]);
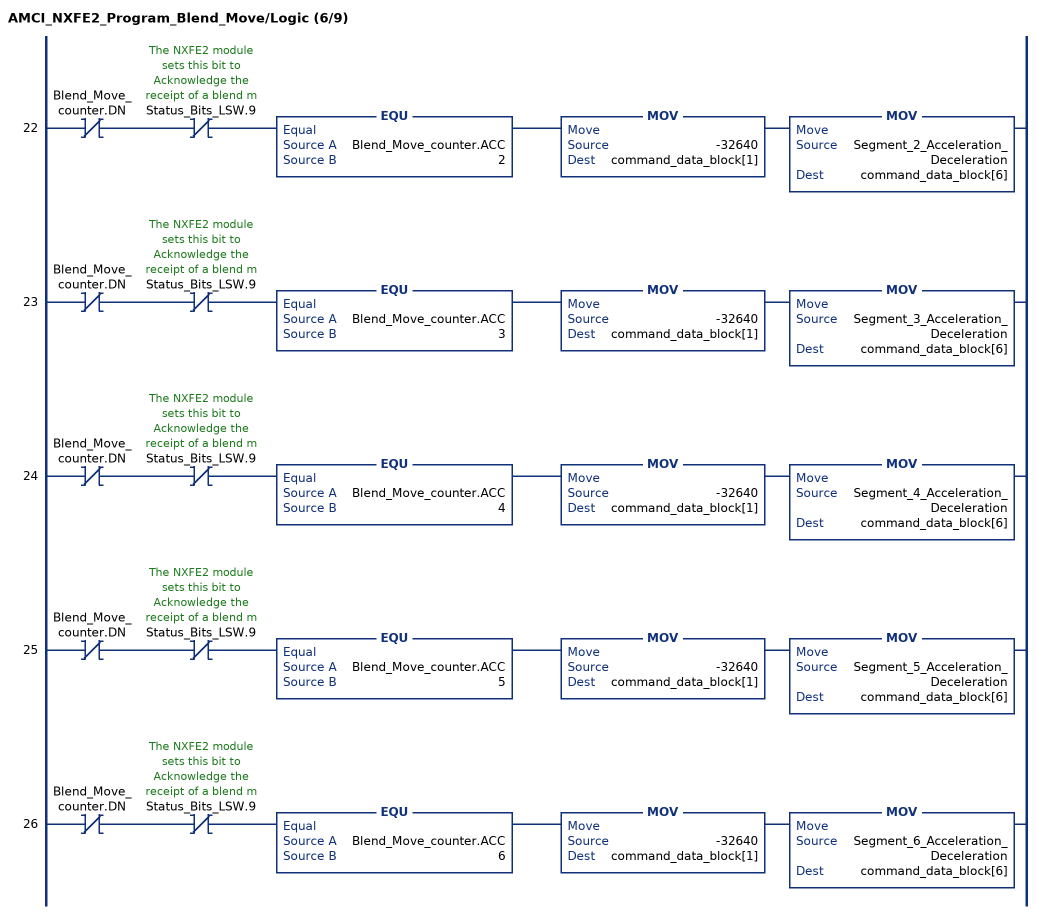
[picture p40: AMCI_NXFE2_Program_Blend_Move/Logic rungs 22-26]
   22: XIO(Blend_Move_counter.DN)XIO(Status_Bits_LSW.9)EQU(Blend_Move_counter.ACC,2)MOV(-32640,command_data_block[1])MOV(Segment_2_Acceleration_Deceleration,command_data_block[6]);
   23: XIO(Blend_Move_counter.DN)XIO(Status_Bits_LSW.9)EQU(Blend_Move_counter.ACC,3)MOV(-32640,command_data_block[1])MOV(Segment_3_Acceleration_Deceleration,command_data_block[6]);
   24: XIO(Blend_Move_counter.DN)XIO(Status_Bits_LSW.9)EQU(Blend_Move_counter.ACC,4)MOV(-32640,command_data_block[1])MOV(Segment_4_Acceleration_Deceleration,command_data_block[6]);
   25: XIO(Blend_Move_counter.DN)XIO(Status_Bits_LSW.9)EQU(Blend_Move_counter.ACC,5)MOV(-32640,command_data_block[1])MOV(Segment_5_Acceleration_Deceleration,command_data_block[6]);
   26: XIO(Blend_Move_counter.DN)XIO(Status_Bits_LSW.9)EQU(Blend_Move_counter.ACC,6)MOV(-32640,command_data_block[1])MOV(Segment_6_Acceleration_Deceleration,command_data_block[6]);
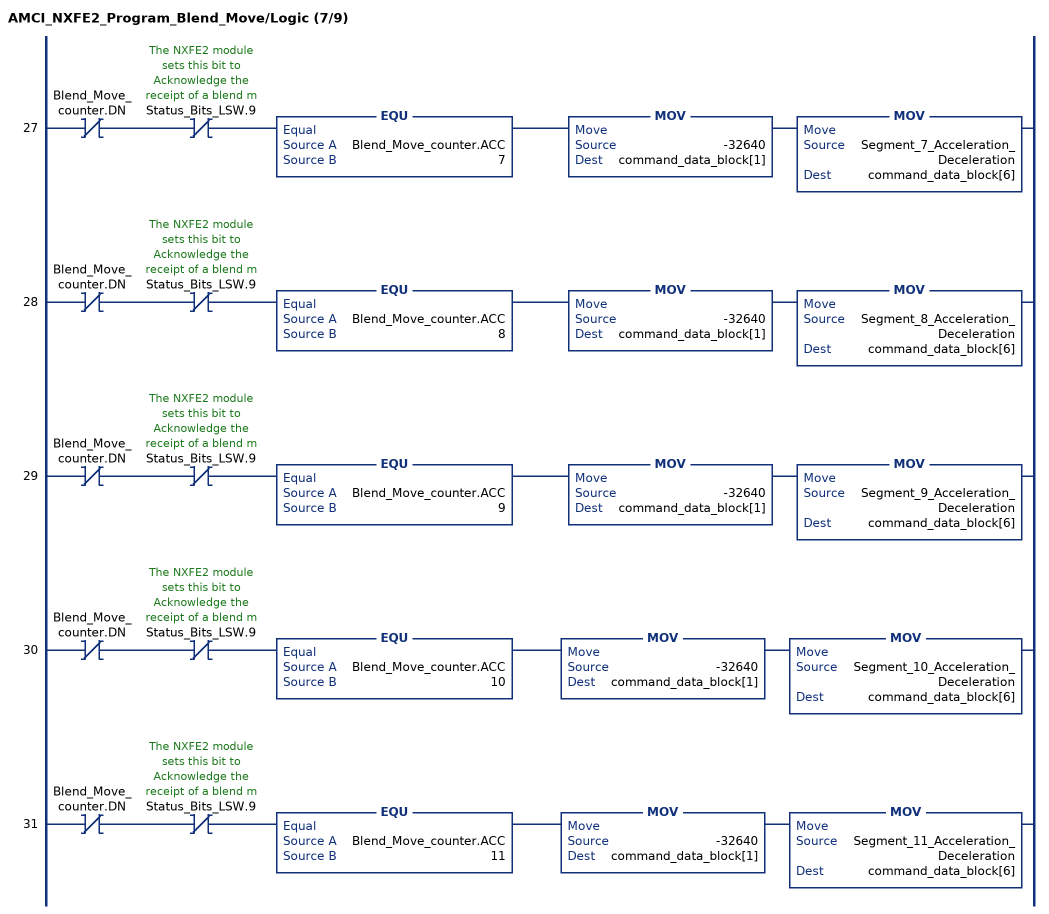
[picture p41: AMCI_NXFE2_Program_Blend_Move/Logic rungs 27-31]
   27: XIO(Blend_Move_counter.DN)XIO(Status_Bits_LSW.9)EQU(Blend_Move_counter.ACC,7)MOV(-32640,command_data_block[1])MOV(Segment_7_Acceleration_Deceleration,command_data_block[6]);
   28: XIO(Blend_Move_counter.DN)XIO(Status_Bits_LSW.9)EQU(Blend_Move_counter.ACC,8)MOV(-32640,command_data_block[1])MOV(Segment_8_Acceleration_Deceleration,command_data_block[6]);
   29: XIO(Blend_Move_counter.DN)XIO(Status_Bits_LSW.9)EQU(Blend_Move_counter.ACC,9)MOV(-32640,command_data_block[1])MOV(Segment_9_Acceleration_Deceleration,command_data_block[6]);
   30: XIO(Blend_Move_counter.DN)XIO(Status_Bits_LSW.9)EQU(Blend_Move_counter.ACC,10)MOV(-32640,command_data_block[1])MOV(Segment_10_Acceleration_Deceleration,command_data_block[6]);
   31: XIO(Blend_Move_counter.DN)XIO(Status_Bits_LSW.9)EQU(Blend_Move_counter.ACC,11)MOV(-32640,command_data_block[1])MOV(Segment_11_Acceleration_Deceleration,command_data_block[6]);
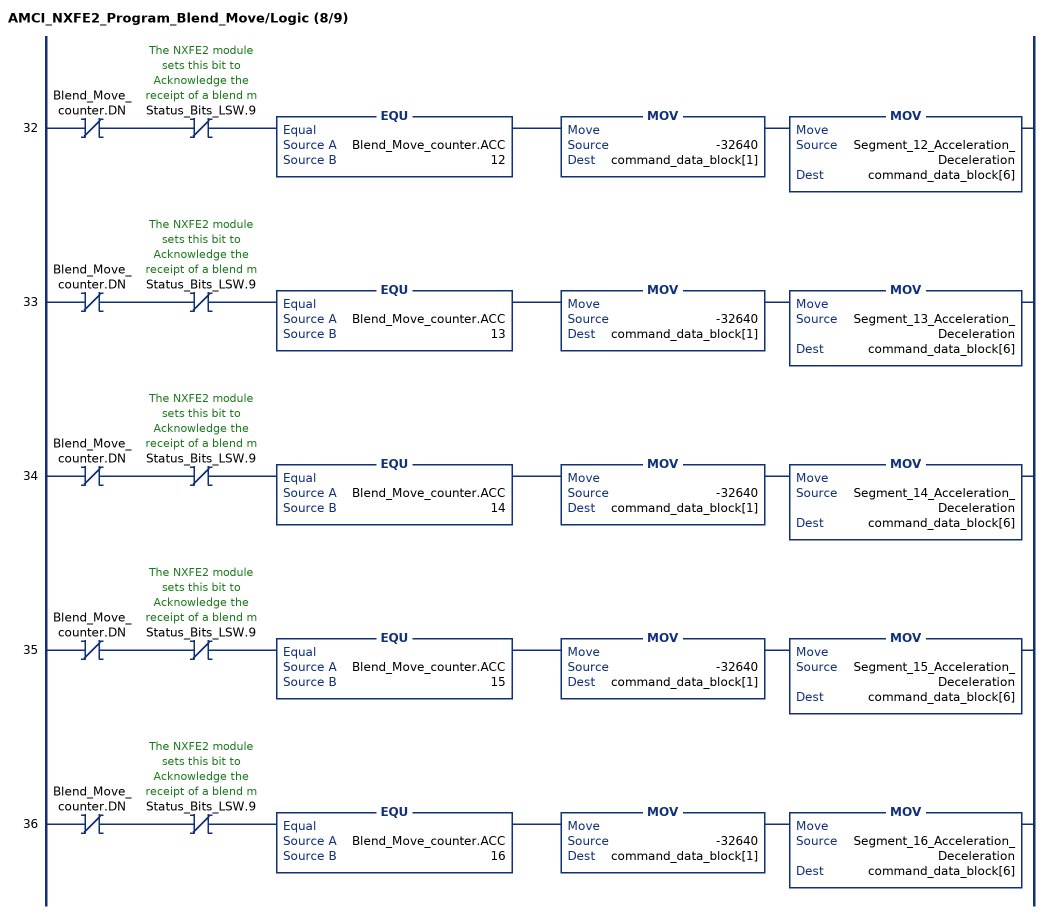
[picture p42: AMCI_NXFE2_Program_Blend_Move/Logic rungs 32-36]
   32: XIO(Blend_Move_counter.DN)XIO(Status_Bits_LSW.9)EQU(Blend_Move_counter.ACC,12)MOV(-32640,command_data_block[1])MOV(Segment_12_Acceleration_Deceleration,command_data_block[6]);
   33: XIO(Blend_Move_counter.DN)XIO(Status_Bits_LSW.9)EQU(Blend_Move_counter.ACC,13)MOV(-32640,command_data_block[1])MOV(Segment_13_Acceleration_Deceleration,command_data_block[6]);
   34: XIO(Blend_Move_counter.DN)XIO(Status_Bits_LSW.9)EQU(Blend_Move_counter.ACC,14)MOV(-32640,command_data_block[1])MOV(Segment_14_Acceleration_Deceleration,command_data_block[6]);
   35: XIO(Blend_Move_counter.DN)XIO(Status_Bits_LSW.9)EQU(Blend_Move_counter.ACC,15)MOV(-32640,command_data_block[1])MOV(Segment_15_Acceleration_Deceleration,command_data_block[6]);
   36: XIO(Blend_Move_counter.DN)XIO(Status_Bits_LSW.9)EQU(Blend_Move_counter.ACC,16)MOV(-32640,command_data_block[1])MOV(Segment_16_Acceleration_Deceleration,command_data_block[6]);
